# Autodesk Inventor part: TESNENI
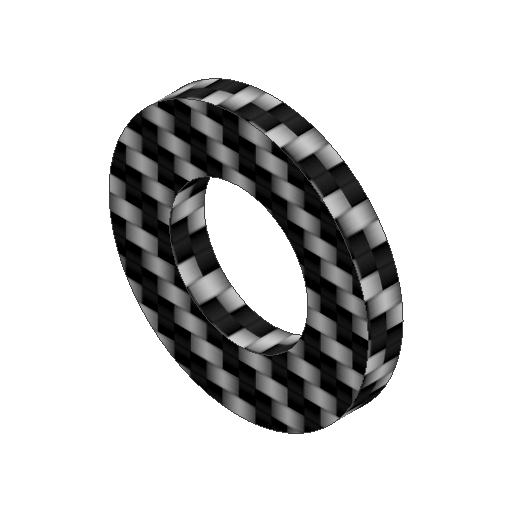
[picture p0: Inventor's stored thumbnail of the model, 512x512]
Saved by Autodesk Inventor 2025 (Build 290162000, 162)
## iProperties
Created: 2025-03
Part Number: TESNENI
Material: CFRP
Document SubType Name: Modeling
Designer: dansp
Mass: 0.361644 g
Surface Area: 3.97411 cm^2
Volume: 0.252898 cm^3
Density: 1.43 g/cm^3
Appearance: Carbon Fiber
Author: dansp
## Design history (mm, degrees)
sketch "Sketch1"
  geometry: L1 (0, 10.5)-(0, -10.5) reference; L2 (-10.5, 0)-(10.5, 0) reference; C1 r 7.5 at (0, 0); C2 r 4 at (0, 0); 1 further point
  constraints: 2 centre point, 2 coincident
  dimensions: "d0" = 8 diameter of C2; "d1" = 15 diameter of C1
extrude "Extrusion1" new body sketch "Sketch1" distance "d2" = 2; taper "d3" = 0 deg
body "Solid1"
